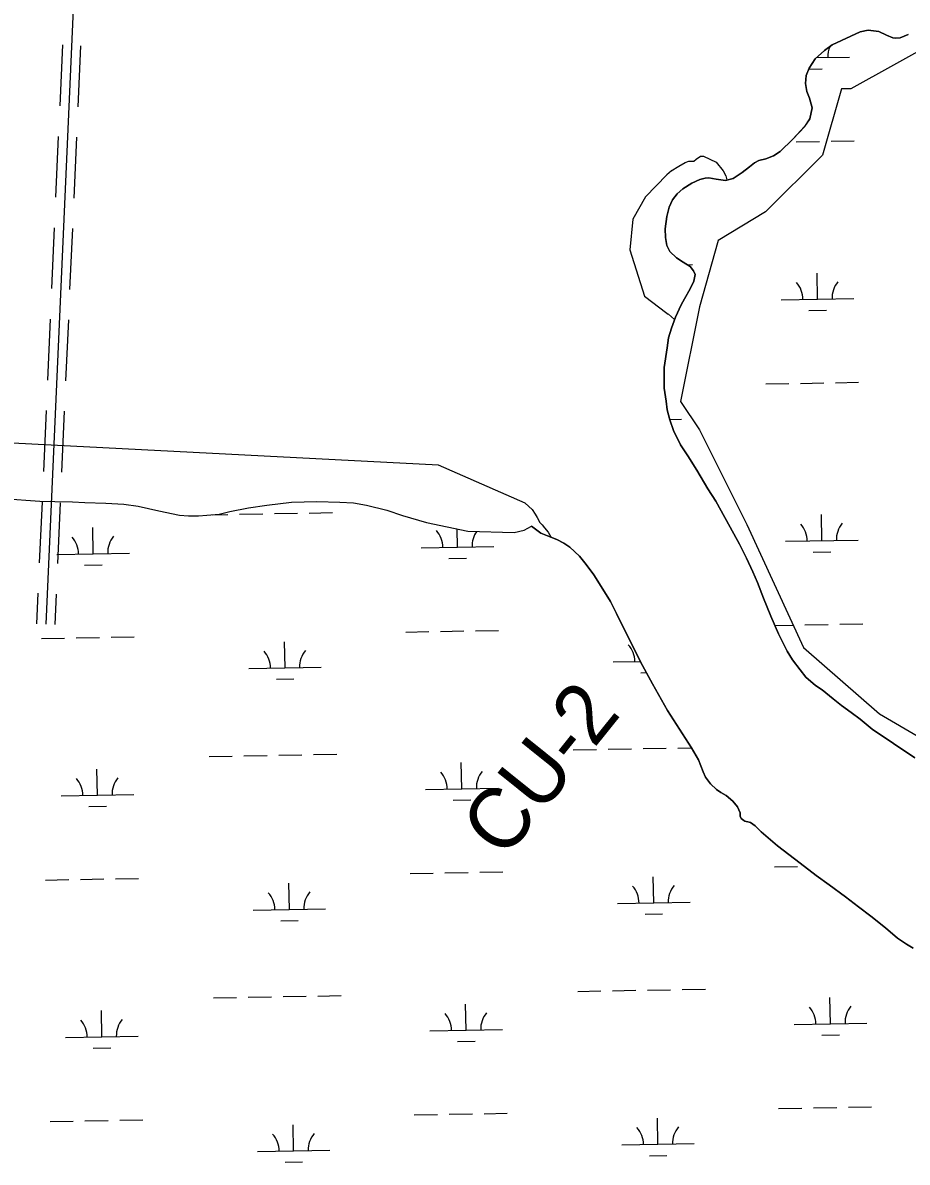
# Model space of a CAD drawing. Extents: x 3914892 to 3953151, y 242587 to 268572.
# Drawn here: x 3942954 to 3944172, y 256318 to 257887 of the extents above; entities that cross this region are included whole.
import ezdxf

# ---------------------------------------------------------------- set-up
doc = ezdxf.new("R2010")
doc.units = 0
for name, color, linetype in [('V-RIVR-EDGE', 7, 'Continuous'), ('V-RIVR-RANG-IDEN', 7, 'Continuous'), ('V-RRAP-DIKE', 7, 'Continuous'), ('V-SITE-VEGE', 7, 'Continuous'), ('V-TOPO-SHOR', 7, 'Continuous'), ('V-WETL-SWMP', 7, 'Continuous')]:
    doc.layers.add(name, color=color, linetype=linetype)

msp = doc.modelspace()

# ---------------------------------------------------------------- linework, layer by layer
at = {"layer": 'V-RIVR-EDGE'}
msp.add_line((3943843.3, 257485.9), (3943851.9, 257478.2), dxfattribs=at)
for points in [[(3943847.3, 257683), (3943857.8, 257689.6), (3943866.5, 257694.8), (3943871.4, 257696.5), (3943878.5, 257696.7), (3943881.5, 257699.3), (3943887.4, 257703.2), (3943891.6, 257703.2), (3943900.4, 257699.3), (3943909.2, 257695), (3943918.9, 257683.3), (3943922.5, 257676.4), (3943923.8, 257670.9)], [(3943847.6, 257683.1), (3943841, 257677.8), (3943811.9, 257647.3), (3943794.4, 257616.7), (3943790.1, 257574.6), (3943810.4, 257510.6), (3943841, 257487.3), (3943843.2, 257486)], [(3943646.1, 257225.4), (3943526.8, 257277.8), (3942290.3, 257341.8), (3942194.3, 257356.4), (3942173.9, 257330.2), (3942171, 257295.3), (3942107, 257251.6), (3942051.8, 257219.6), (3941990.7, 257210.9), (3941909.2, 257231.3), (3941856.8, 257254.5), (3941787, 257280.7), (3941720.1, 257292.4), (3941650.3, 257277.8), (3941627, 257266.2), (3941604.5, 257254.1)], [(3943645.9, 257225.5), (3943655.6, 257216.9), (3943659.7, 257210.2), (3943662.7, 257205.7), (3943666.2, 257198.7), (3943669.4, 257195.4), (3943672.6, 257191.7), (3943677.7, 257185.3), (3943681.3, 257178.9)]]:
    msp.add_lwpolyline(points, dxfattribs=at)
at = {"layer": 'V-RRAP-DIKE'}
for points in [[(3942986.1, 257058.8), (3943063.5, 258794.9)], [(3943005.4, 257772.7), (3943009.1, 257856.6)], [(3943030.4, 257771.5), (3943034.1, 257855.5)], [(3942999.8, 257646.8), (3943003.5, 257730.7)], [(3943024.8, 257645.7), (3943028.5, 257729.6)], [(3942994.2, 257520.9), (3942997.9, 257604.8)], [(3943019.1, 257519.8), (3943022.9, 257603.7)], [(3942988.5, 257395), (3942992.3, 257479)], [(3943013.5, 257393.9), (3943017.3, 257477.8)], [(3942982.9, 257269.2), (3942986.7, 257353.1)], [(3943007.9, 257268), (3943011.7, 257352)], [(3942977.3, 257143.3), (3942981.1, 257227.2)], [(3943002.3, 257142.2), (3943006, 257226.1)], [(3942973.6, 257059.4), (3942975.4, 257101.3)], [(3942998.6, 257058.3), (3943000.4, 257100.2)]]:
    msp.add_lwpolyline(points, dxfattribs=at)
at = {"layer": 'V-SITE-VEGE'}
msp.add_lwpolyline([(3944212.1, 257861.3), (3944094.7, 257796.1), (3944081.7, 257796.1), (3944055.6, 257704.8), (3943977.3, 257626.5), (3943912.1, 257587.4), (3943886, 257496.1), (3943860, 257365.6), (3943886, 257326.5), (3943951.3, 257196.1), (3944029.5, 257026.5), (3944133.9, 256935.2), (3944759.9, 256570)], dxfattribs=at)
at = {"layer": 'V-TOPO-SHOR'}
for points in [[(3944173.5, 257870.9), (3944162.7, 257866.2), (3944155.6, 257865.7), (3944152.4, 257866.2), (3944143.6, 257869.9), (3944133.4, 257875.3), (3944118.4, 257876.8), (3944107.3, 257874.5), (3944069, 257856.6), (3944058.2, 257848.8), (3944045.3, 257837.4), (3944037.3, 257824.5), (3944033.2, 257814.4), (3944032.3, 257803.3), (3944033.9, 257792.5), (3944037.5, 257783.4), (3944041.5, 257770), (3944038.3, 257754.7), (3944031, 257744.3), (3944014.6, 257726.9), (3943997.5, 257709.9), (3943988.1, 257704), (3943977.6, 257699.7), (3943968, 257697.3), (3943961.9, 257694.3), (3943955, 257688.9), (3943945, 257680.9), (3943932.6, 257672.8), (3943921.9, 257670.1), (3943909.3, 257671.6), (3943899.2, 257673.4), (3943894.1, 257673.3), (3943886.7, 257671.3), (3943875.5, 257666), (3943863.1, 257658.4), (3943855.2, 257651.4), (3943849, 257643.3), (3943844.4, 257633.2), (3943841.4, 257620.4), (3943838.8, 257603.4), (3943839.2, 257591.4), (3943841.2, 257580.4), (3943845.5, 257571.9), (3943854.6, 257563.3), (3943863.5, 257557.3), (3943873.5, 257551.2), (3943878.1, 257545.5), (3943880.1, 257540.2), (3943878.5, 257531.4), (3943873.2, 257520.5), (3943865.4, 257507.1), (3943860.9, 257498.4), (3943853.2, 257481.7), (3943847.5, 257466.6), (3943843.7, 257453.4)], [(3943843.7, 257453.4), (3943841.8, 257439.5), (3943837.5, 257412.4), (3943837.7, 257384), (3943840.1, 257365.8), (3943841.8, 257353.8), (3943845.4, 257340.4), (3943850.2, 257325.4), (3943860, 257305.6), (3943870.3, 257290.5), (3943882.4, 257271.1), (3943897.7, 257245.2), (3943908.8, 257228.2), (3943933.6, 257183.3), (3943941.3, 257168.9), (3943951.1, 257149.5), (3943959.7, 257131.1), (3943966, 257116.4), (3943974.4, 257094.4), (3943984.6, 257070), (3943995.1, 257045.6), (3944007.1, 257021.6), (3944014.5, 257009.9), (3944024.8, 256996), (3944032.5, 256986), (3944045.8, 256974.2), (3944055.1, 256968.3), (3944070.5, 256956.1), (3944081.7, 256947), (3944095.3, 256937.3), (3944107.6, 256928.1), (3944124, 256914.1), (3944182.7, 256874.8)], [(3944180.5, 256612.6), (3944171.4, 256618.2), (3944158.7, 256626.4), (3944142.2, 256640.6), (3944122.3, 256656.6), (3944105.2, 256669.3), (3944087.1, 256683.2), (3944064.6, 256699.6), (3944047, 256712.6), (3944024.9, 256729.6), (3943993.7, 256753.5), (3943971.1, 256773), (3943962.8, 256781), (3943956.6, 256785.7), (3943954.7, 256786.3), (3943948.4, 256787.5), (3943947.1, 256788.4), (3943943.8, 256791.2), (3943942.4, 256794.5), (3943942, 256798.8), (3943938.4, 256807.3), (3943932, 256815.2), (3943923.1, 256822.9), (3943915.7, 256827), (3943909.5, 256831.3), (3943901.4, 256838.8), (3943894.4, 256848), (3943891.1, 256855.6), (3943884.9, 256871.8), (3943875.1, 256888.4), (3943867.1, 256901.3), (3943842, 256940.1), (3943821.3, 256976.5), (3943805, 257007.1), (3943793, 257031.1), (3943781.1, 257054.9), (3943772, 257073.3), (3943763.8, 257090.1), (3943753.1, 257106.9), (3943740.8, 257126.7), (3943729.9, 257140.8), (3943720.8, 257152.3), (3943707.8, 257164.7), (3943699.4, 257170.4), (3943689.6, 257175.6), (3943676.9, 257180.6), (3943667.8, 257184), (3943654.8, 257193.6)]]:
    msp.add_lwpolyline(points, dxfattribs=at)
at = {"layer": 'V-WETL-SWMP'}
for p, q in [((3944107.3, 257874.5), (3944118.4, 257876.8)), ((3944118.4, 257876.8), (3944133.4, 257875.3)), ((3944069, 257856.6), (3944107.3, 257874.5)), ((3944133.4, 257875.3), (3944143.6, 257869.9)), ((3944143.6, 257869.9), (3944152.4, 257866.2)), ((3944152.4, 257866.2), (3944155.6, 257865.7)), ((3944155.6, 257865.7), (3944162.7, 257866.2)), ((3944162.7, 257866.2), (3944173.5, 257870.9)), ((3944045.3, 257837.4), (3944058.2, 257848.8)), ((3944058.2, 257848.8), (3944069, 257856.6)), ((3944037.3, 257824.5), (3944045.3, 257837.4)), ((3944047.1, 257839.1), (3944092.8, 257839.9)), ((3944032.3, 257803.3), (3944033.2, 257814.4)), ((3944033.2, 257814.4), (3944037.3, 257824.5)), ((3944036.8, 257823.4), (3944055, 257823.8)), ((3944033.9, 257792.5), (3944032.3, 257803.3)), ((3944037.5, 257783.4), (3944033.9, 257792.5)), ((3944041.5, 257770), (3944037.5, 257783.4)), ((3944038.3, 257754.7), (3944041.5, 257770)), ((3944031.1, 257744.3), (3944038.3, 257754.7)), ((3944014.6, 257726.9), (3944031.1, 257744.3)), ((3943997.5, 257709.9), (3944014.6, 257726.9)), ((3944019.4, 257723.1), (3944051.4, 257723.7)), ((3944067.4, 257724), (3944099.4, 257724.6)), ((3943977.6, 257699.7), (3943988.1, 257704)), ((3943988.1, 257704), (3943997.5, 257709.9)), ((3943945, 257680.9), (3943955, 257688.9)), ((3943955, 257688.9), (3943961.9, 257694.3)), ((3943961.9, 257694.3), (3943968, 257697.3)), ((3943968, 257697.3), (3943977.6, 257699.7)), ((3943886.7, 257671.3), (3943894.1, 257673.3)), ((3943894.1, 257673.3), (3943899.2, 257673.4)), ((3943899.2, 257673.4), (3943909.3, 257671.6)), ((3943921.9, 257670.1), (3943932.6, 257672.7)), ((3943932.6, 257672.7), (3943945, 257680.9)), ((3943855.2, 257651.4), (3943863.1, 257658.4)), ((3943863.1, 257658.4), (3943875.5, 257666)), ((3943875.5, 257666), (3943886.7, 257671.3)), ((3943909.3, 257671.6), (3943921.9, 257670.1)), ((3943844.4, 257633.2), (3943849, 257643.3)), ((3943849, 257643.3), (3943855.2, 257651.4)), ((3943841.4, 257620.4), (3943844.4, 257633.2)), ((3943838.8, 257603.4), (3943841.4, 257620.4)), ((3943839.2, 257591.4), (3943838.8, 257603.4)), ((3943841.2, 257580.4), (3943839.2, 257591.4)), ((3943845.5, 257571.9), (3943841.2, 257580.4)), ((3943854.6, 257563.3), (3943845.5, 257571.9)), ((3943863.5, 257557.3), (3943854.6, 257563.3)), ((3943873.5, 257551.2), (3943863.5, 257557.3)), ((3943869, 257553.9), (3943876.5, 257554)), ((3943878.1, 257545.5), (3943873.5, 257551.2)), ((3943873.2, 257520.5), (3943878.5, 257531.4)), ((3943880.1, 257540.2), (3943878.1, 257545.5)), ((3943878.5, 257531.4), (3943880.1, 257540.2)), ((3944048.7, 257506.4), (3944048.1, 257542.4)), ((3943865.4, 257507.1), (3943873.2, 257520.5)), ((3943860.9, 257498.4), (3943865.4, 257507.1)), ((3943998.7, 257505.5), (3944098.7, 257507.3)), ((3943853.2, 257481.7), (3943860.9, 257498.4)), ((3944037, 257490.7), (3944061, 257491.2)), ((3943847.5, 257466.6), (3943853.2, 257481.7)), ((3943841.8, 257439.5), (3943843.7, 257453.4)), ((3943843.7, 257453.4), (3943847.5, 257466.6)), ((3943837.5, 257412.4), (3943841.8, 257439.5)), ((3943837.7, 257384), (3943837.5, 257412.4)), ((3943977.4, 257389.6), (3944009.4, 257390.2)), ((3944025.4, 257390.5), (3944057.4, 257391.1)), ((3944073.4, 257391.4), (3944105.4, 257391.9)), ((3943840.1, 257365.8), (3943837.7, 257384)), ((3943841.8, 257353.8), (3943840.1, 257365.8)), ((3943845.4, 257340.4), (3943841.8, 257353.8)), ((3943845.3, 257340.8), (3943861.2, 257341.1)), ((3943850.2, 257325.4), (3943845.4, 257340.4)), ((3943860, 257305.6), (3943850.2, 257325.4)), ((3943870.3, 257290.5), (3943860, 257305.6)), ((3943882.4, 257271.1), (3943870.3, 257290.5)), ((3943897.7, 257245.2), (3943882.4, 257271.1)), ((3943908.8, 257228.2), (3943897.7, 257245.2)), ((3942926.7, 257232.1), (3942977.5, 257228.3)), ((3942977.5, 257228.3), (3942998.3, 257227.9)), ((3942998.3, 257227.9), (3943022.7, 257227.1)), ((3943022.7, 257227.1), (3943039.4, 257226.6)), ((3943039.4, 257226.6), (3943068.7, 257225.3)), ((3943068.7, 257225.3), (3943093.5, 257224.2)), ((3943093.5, 257224.2), (3943112.9, 257221.2)), ((3943112.9, 257221.2), (3943141.6, 257214.8)), ((3943239.2, 257213.8), (3943264.8, 257218.9)), ((3943264.8, 257218.9), (3943290.3, 257222.9)), ((3943290.3, 257222.9), (3943324.3, 257226.9)), ((3943324.3, 257226.9), (3943359.3, 257227.8)), ((3943359.3, 257227.8), (3943390.7, 257226.7)), ((3943390.7, 257226.7), (3943409.7, 257225.7)), ((3943409.7, 257225.7), (3943427.3, 257222.7)), ((3943427.3, 257222.7), (3943455.6, 257215.9)), ((3943933.6, 257183.3), (3943908.8, 257228.2)), ((3943141.6, 257214.8), (3943170, 257208.9)), ((3943170, 257208.9), (3943182.2, 257208.2)), ((3943182.2, 257208.2), (3943195.9, 257208)), ((3943195.9, 257208), (3943207.7, 257208.8)), ((3943207.7, 257208.8), (3943224.4, 257210.3)), ((3943215.4, 257209.5), (3943236.7, 257209.9)), ((3943224.4, 257210.3), (3943239.2, 257213.8)), ((3943252.7, 257210.1), (3943284.7, 257210.7)), ((3943300.7, 257211), (3943332.6, 257211.6)), ((3943348.6, 257211.9), (3943380.6, 257212.4)), ((3943455.6, 257215.9), (3943477, 257208.6)), ((3943477, 257208.6), (3943510.2, 257198.8)), ((3944054.7, 257173.7), (3944054, 257209.7)), ((3943051, 257155.8), (3943050.4, 257191.8)), ((3943510.2, 257198.8), (3943567.3, 257186.9)), ((3943552.8, 257164.8), (3943552.4, 257190)), ((3943567.3, 257186.9), (3943631.1, 257185.2)), ((3943631.1, 257185.2), (3943644.6, 257188.1)), ((3943644.6, 257188.1), (3943654.8, 257193.6)), ((3943654.8, 257193.6), (3943667.8, 257184)), ((3943667.8, 257184), (3943676.9, 257180.6)), ((3943676.9, 257180.6), (3943689.6, 257175.6)), ((3943689.6, 257175.6), (3943699.4, 257170.4)), ((3943699.4, 257170.4), (3943707.8, 257164.7)), ((3943941.3, 257168.9), (3943933.6, 257183.3)), ((3944004.7, 257172.9), (3944104.7, 257174.6)), ((3943001, 257154.9), (3943101, 257156.7)), ((3943502.8, 257163.9), (3943602.8, 257165.7)), ((3943707.8, 257164.7), (3943720.8, 257152.3)), ((3943951.1, 257149.5), (3943941.3, 257168.9)), ((3944042.9, 257158.1), (3944066.9, 257158.5)), ((3943039.3, 257140.1), (3943063.3, 257140.6)), ((3943541.1, 257149.1), (3943565.1, 257149.6)), ((3943720.8, 257152.3), (3943729.9, 257140.8)), ((3943729.9, 257140.8), (3943740.8, 257126.7)), ((3943959.7, 257131.1), (3943951.1, 257149.5)), ((3943740.8, 257126.7), (3943753.1, 257106.9)), ((3943966, 257116.4), (3943959.7, 257131.1)), ((3943974.4, 257094.4), (3943966, 257116.4)), ((3943753.1, 257106.9), (3943763.8, 257090.1)), ((3943984.6, 257070), (3943974.4, 257094.4)), ((3943763.8, 257090.1), (3943772, 257073.3)), ((3943772, 257073.3), (3943781.1, 257054.9)), ((3943995.1, 257045.6), (3943984.6, 257070)), ((3943481.5, 257048), (3943513.5, 257048.6)), ((3943529.5, 257048.9), (3943561.5, 257049.5)), ((3943577.5, 257049.8), (3943609.5, 257050.3)), ((3943781.1, 257054.9), (3943793, 257031.1)), ((3943990.1, 257057.1), (3944015.3, 257057.6)), ((3944007.1, 257021.6), (3943995.1, 257045.6)), ((3944031.3, 257057.9), (3944063.3, 257058.5)), ((3944079.3, 257058.7), (3944111.3, 257059.3)), ((3942979.7, 257039.1), (3943011.7, 257039.6)), ((3943027.7, 257039.9), (3943059.7, 257040.5)), ((3943075.7, 257040.8), (3943107.7, 257041.4)), ((3943315.3, 256998.6), (3943314.7, 257034.6)), ((3943793, 257031.1), (3943805, 257007.1)), ((3944014.5, 257009.9), (3944007.1, 257021.6)), ((3943265.3, 256997.7), (3943365.3, 256999.5)), ((3943767.1, 257006.7), (3943804.9, 257007.4)), ((3943805, 257007.1), (3943821.3, 256976.5)), ((3944024.8, 256996), (3944014.5, 257009.9)), ((3943303.6, 256983), (3943327.6, 256983.4)), ((3943805.4, 256992), (3943813, 256992.1)), ((3944032.5, 256986), (3944024.8, 256996)), ((3944045.8, 256974.2), (3944032.5, 256986)), ((3943821.3, 256976.5), (3943842, 256940.1)), ((3944055.1, 256968.3), (3944045.8, 256974.2)), ((3944070.5, 256956.1), (3944055.1, 256968.3)), ((3944081.7, 256947), (3944070.5, 256956.1)), ((3943842, 256940.1), (3943867.1, 256901.3)), ((3944095.3, 256937.3), (3944081.7, 256947)), ((3944107.6, 256928.1), (3944095.3, 256937.3)), ((3944124, 256914.1), (3944107.6, 256928.1)), ((3944182.7, 256874.8), (3944124, 256914.1)), ((3943808.4, 256887.4), (3943840.4, 256887.9)), ((3943856.4, 256888.2), (3943875.1, 256888.6)), ((3943867.1, 256901.3), (3943875.1, 256888.4)), ((3943875.1, 256888.4), (3943884.9, 256871.8)), ((3943210.6, 256876.7), (3943242.6, 256877.2)), ((3943258.6, 256877.5), (3943290.6, 256878.1)), ((3943306.6, 256878.4), (3943338.6, 256879)), ((3943354.6, 256879.2), (3943386.6, 256879.8)), ((3943712.4, 256885.6), (3943744.4, 256886.2)), ((3943760.4, 256886.5), (3943792.4, 256887.1)), ((3943884.9, 256871.8), (3943891.1, 256855.6)), ((3943057, 256823.2), (3943056.3, 256859.2)), ((3943558.8, 256832.1), (3943558.1, 256868.1)), ((3943891.1, 256855.6), (3943894.4, 256848)), ((3943894.4, 256848), (3943901.4, 256838.8)), ((3943508.8, 256831.3), (3943608.8, 256833)), ((3943901.4, 256838.8), (3943909.5, 256831.3)), ((3943909.5, 256831.3), (3943915.7, 256827)), ((3943915.7, 256827), (3943923.1, 256822.9)), ((3943007, 256822.3), (3943107, 256824.1)), ((3943547.1, 256816.5), (3943571.1, 256816.9)), ((3943923.1, 256822.9), (3943932, 256815.2)), ((3943932, 256815.2), (3943938.4, 256807.3)), ((3943045.2, 256807.5), (3943069.2, 256808)), ((3943938.4, 256807.3), (3943942, 256798.8)), ((3943942, 256798.8), (3943942.4, 256794.5)), ((3943942.4, 256794.5), (3943943.8, 256791.2)), ((3943943.8, 256791.2), (3943947.1, 256788.4)), ((3943947.1, 256788.4), (3943948.4, 256787.5)), ((3943948.4, 256787.5), (3943954.7, 256786.3)), ((3943954.7, 256786.3), (3943956.6, 256785.7)), ((3943956.6, 256785.7), (3943962.8, 256781)), ((3943962.8, 256781), (3943971.1, 256773)), ((3943971.1, 256773), (3943993.7, 256753.5)), ((3943993.7, 256753.5), (3944024.9, 256729.6)), ((3943487.5, 256715.4), (3943519.5, 256716)), ((3943535.5, 256716.3), (3943567.4, 256716.8)), ((3943583.4, 256717.1), (3943615.4, 256717.7)), ((3943989.3, 256724.4), (3944021.3, 256725)), ((3944024.9, 256729.6), (3944047, 256712.6)), ((3942985.6, 256706.4), (3943017.6, 256707)), ((3943033.6, 256707.3), (3943065.6, 256707.9)), ((3943081.6, 256708.2), (3943113.6, 256708.7)), ((3943321.3, 256666), (3943320.6, 256702)), ((3943823.1, 256675), (3943822.4, 256711)), ((3944047, 256712.6), (3944064.6, 256699.6)), ((3944064.6, 256699.6), (3944087.1, 256683.2)), ((3943773.1, 256674.1), (3943873.1, 256675.9)), ((3944087.1, 256683.2), (3944105.2, 256669.3)), ((3944105.2, 256669.3), (3944122.3, 256656.6)), ((3943271.3, 256665.1), (3943371.2, 256666.9)), ((3943811.4, 256659.3), (3943835.4, 256659.8)), ((3944122.3, 256656.6), (3944142.2, 256640.6)), ((3943309.5, 256650.4), (3943333.5, 256650.8)), ((3944142.2, 256640.6), (3944158.7, 256626.4)), ((3944158.7, 256626.4), (3944171.4, 256618.2)), ((3944171.4, 256618.2), (3944180.5, 256612.6)), ((3943216.6, 256544), (3943248.6, 256544.6)), ((3943264.6, 256544.9), (3943296.6, 256545.5)), ((3943312.6, 256545.8), (3943344.6, 256546.3)), ((3943360.5, 256546.6), (3943392.5, 256547.2)), ((3943718.4, 256553), (3943750.4, 256553.6)), ((3943766.4, 256553.9), (3943798.4, 256554.5)), ((3943814.4, 256554.7), (3943846.4, 256555.3)), ((3943862.4, 256555.6), (3943894.4, 256556.2)), ((3944066.6, 256508.5), (3944065.9, 256544.5)), ((3943062.9, 256490.5), (3943062.3, 256526.5)), ((3943564.7, 256499.5), (3943564.1, 256535.5)), ((3943514.7, 256498.6), (3943614.7, 256500.4)), ((3944016.6, 256507.6), (3944116.6, 256509.4)), ((3943012.9, 256489.7), (3943112.9, 256491.4)), ((3943553, 256483.9), (3943577, 256484.3)), ((3944054.8, 256492.9), (3944078.8, 256493.3)), ((3943051.2, 256474.9), (3943075.2, 256475.3)), ((3943995.2, 256391.8), (3944027.2, 256392.3)), ((3944043.2, 256392.6), (3944075.2, 256393.2)), ((3944091.2, 256393.5), (3944123.2, 256394.1)), ((3942991.6, 256373.8), (3943023.6, 256374.4)), ((3943039.6, 256374.7), (3943071.6, 256375.2)), ((3943087.6, 256375.5), (3943119.6, 256376.1)), ((3943493.4, 256382.8), (3943525.4, 256383.4)), ((3943541.4, 256383.7), (3943573.4, 256384.2)), ((3943589.4, 256384.5), (3943621.4, 256385.1)), ((3943829, 256342.4), (3943828.4, 256378.4)), ((3943327.2, 256333.4), (3943326.6, 256369.4)), ((3943779, 256341.5), (3943879, 256343.3)), ((3943277.2, 256332.5), (3943377.2, 256334.3)), ((3943817.3, 256326.7), (3943841.3, 256327.2)), ((3943315.5, 256317.7), (3943339.5, 256318.2))]:
    msp.add_line(p, q, dxfattribs=at)
for centre, start, end in [((3944098, 257840.5), 157.2263, 181.7968), ((3943993.5, 257505.9), 0.2532, 41.7968), ((3944103.9, 257507.8), 140.2532, 181.7968), ((3943497.6, 257164.3), 0.2532, 41.7968), ((3943608.1, 257166.2), 144.6647, 181.7968), ((3943999.4, 257173.2), 0.2532, 41.7968), ((3944109.9, 257175.2), 140.2532, 181.7968), ((3942995.8, 257155.3), 0.2532, 41.7968), ((3943106.2, 257157.3), 140.2532, 181.7968), ((3943761.9, 257007.1), 0.2532, 41.7968), ((3943260.1, 256998.1), 0.2532, 41.7968), ((3943370.5, 257000.1), 140.2532, 181.7968), ((3943614, 256833.6), 140.2532, 181.7968), ((3943001.7, 256822.7), 0.2532, 41.7968), ((3943112.2, 256824.6), 140.2532, 181.7968), ((3943503.5, 256831.6), 0.2532, 41.7968), ((3943266, 256665.5), 0.2532, 41.7968), ((3943376.5, 256667.5), 140.2532, 181.7968), ((3943767.8, 256674.5), 0.2532, 41.7968), ((3943878.3, 256676.4), 140.2532, 181.7968), ((3944011.3, 256508), 0.2532, 41.7968), ((3944121.8, 256510), 140.2532, 181.7968), ((3943007.7, 256490), 0.2532, 41.7968), ((3943118.1, 256492), 140.2532, 181.7968), ((3943509.5, 256499), 0.2532, 41.7968), ((3943620, 256501), 140.2532, 181.7968), ((3943272, 256332.9), 0.2532, 41.7968), ((3943382.4, 256334.8), 140.2532, 181.7968), ((3943773.8, 256341.9), 0.2532, 41.7968), ((3943884.3, 256343.8), 140.2532, 181.7968)]:
    msp.add_arc(centre, 35.2, start, end, dxfattribs=at)

# ---------------------------------------------------------------- texts
at = {"layer": 'V-RIVR-RANG-IDEN'}
msp.add_text('CU-2  ', height=83, rotation=51.2303, dxfattribs=at).set_placement((3943617.2, 256733.1))

doc.saveas('drawing.dxf')
